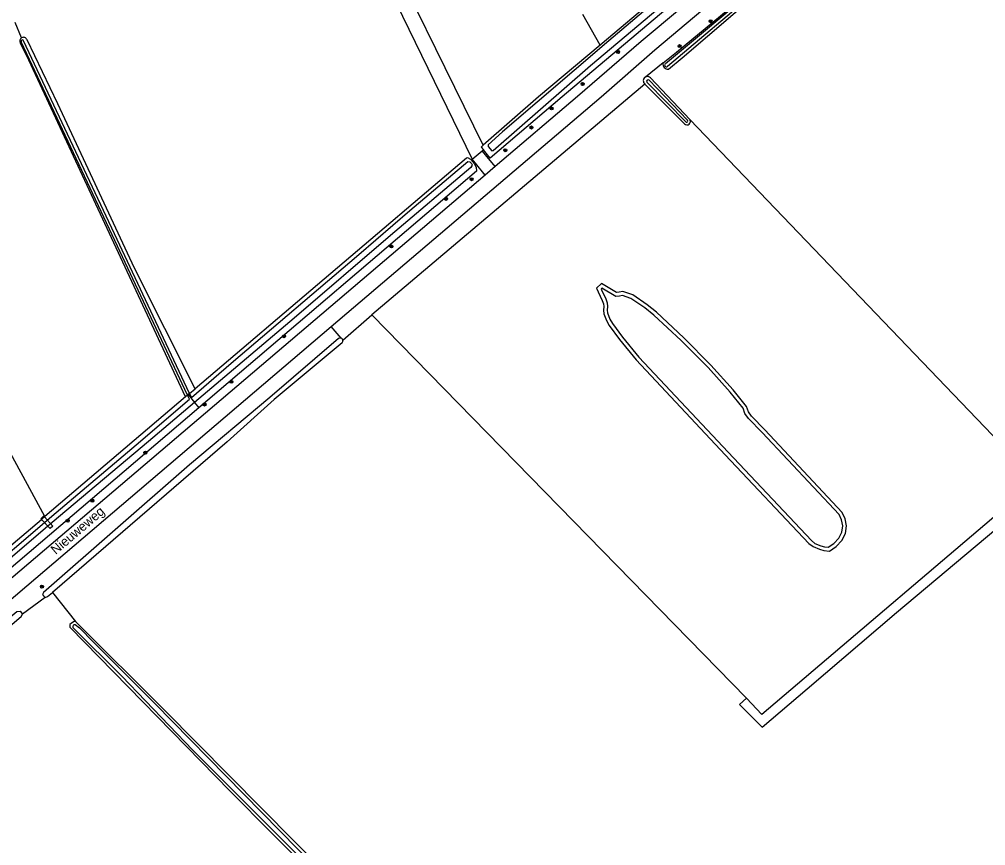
# Model space of a CAD drawing. Extents: x 141000 to 143000, y 400580 to 403500.
# Drawn here: x 141831.6 to 142087.7, y 402801.5 to 403020.5 of the extents above; entities that cross this region are included whole.
import ezdxf

# ---------------------------------------------------------------- set-up
doc = ezdxf.new("R2010")
doc.units = 0
for name, color, linetype in [('gg-afsc-erfafscheiding', 7, 'Continuous'), ('gg-anno-openbare ruimte label', 7, 'Continuous'), ('gg-knt-bronhoudergrens', 7, 'Continuous'), ('gg-knt-onverhard', 7, 'Continuous'), ('gg-knt-verharding', 7, 'Continuous'), ('gg-knt-verharding nz', 7, 'Continuous'), ('gg-kntw-bovenkant insteek waterloop', 7, 'Continuous'), ('gg-kntw-waterlijn', 7, 'Continuous'), ('gg-kwrk-kunstwerk niveau 01', 7, 'Continuous'), ('gt-grn-groengrens', 7, 'Continuous'), ('gt-grn-groengrens NZ', 7, 'Continuous'), ('gt-grn-vlakafsluiter', 7, 'Continuous'), ('gt-symb-boom', 7, 'Continuous')]:
    doc.layers.add(name, color=color, linetype=linetype)

# ---------------------------------------------------------------- blocks, each defined once
blk = doc.blocks.new('gt0-BOOM')
at = {"layer": 'gt-symb-boom'}
for radius in [0.4, 0.2]:
    blk.add_circle((0, 0), radius, dxfattribs=at)

msp = doc.modelspace()

# ---------------------------------------------------------------- linework, layer by layer
at = {"layer": 'gg-afsc-erfafscheiding'}
msp.add_line((141954.24, 402985.64), (141954.6, 402985.93), dxfattribs=at)
at = {"layer": 'gg-knt-bronhoudergrens'}
for p, q in [((141985.53, 403013.64), (141980.91, 403021.8)), ((141838.43, 402888.78), (141779.26, 402997.04)), ((142101.08, 402898.11), (142009.26, 402994.01)), ((141951.61, 402983.49), (141951.33, 402983.25)), ((141917.32, 402935.51), (141925.02, 402942.19)), ((142024.33, 402840.61), (141925.02, 402942.19)), ((141838.51, 402867.33), (141832.48, 402862.85))]:
    msp.add_line(p, q, dxfattribs=at)
for points in [[(141954.53, 402987.13), (141924.4, 403048.52), (141955.72, 403068.45)], [(141886.23, 403053.07), (141911.29, 403066.42), (141951.61, 402983.49)], [(142024.33, 402840.61), (142022.47, 402838.91), (142028.48, 402832.9), (142040.38, 402843.06), (142064.01, 402863.29), (142090.33, 402885.42), (142125.51, 402915.15), (142155.54, 402940.68), (142156.57, 402939.65), (142164.47, 402946.13), (142180.6, 402935.22), (142189.91, 402945.16)], [(142101.08, 402898.11), (142028.36, 402836.3), (142024.33, 402840.61)]]:
    msp.add_lwpolyline(points, dxfattribs=at)
at = {"layer": 'gg-knt-onverhard'}
for p, q in [((141832.25, 403015.61), (141830.54, 403019.7)), ((141840.41, 402868.64), (141846.55, 402860.98))]:
    msp.add_line(p, q, dxfattribs=at)
at = {"layer": 'gg-knt-verharding'}
for p, q in [((141951.61, 402983.49), (141954.24, 402985.64)), ((141955.04, 402979.19), (141652.93, 402722.12)), ((141655.26, 402718.53), (141914.25, 402939.09))]:
    msp.add_line(p, q, dxfattribs=at)
for points in [[(142113.94, 403114.98), (142069.01, 403075.7), (142040.23, 403051.3), (141996.37, 403014.63), (141979.56, 403000.04), (141957.73, 402981.47)], [(141914.25, 402939.09), (141985.78, 403000), (142000, 403012.42), (142042.58, 403048.33), (142071.63, 403072.64), (142109.08, 403104.56)], [(141957.73, 402981.47), (141955.12, 402984.6), (141954.24, 402985.64)], [(141955.04, 402979.19), (141952.51, 402982.36), (141951.61, 402983.49)]]:
    msp.add_lwpolyline(points, dxfattribs=at)
at = {"layer": 'gg-knt-verharding nz'}
msp.add_line((141957.73, 402981.47), (141955.04, 402979.19), dxfattribs=at)
at = {"layer": 'gg-kntw-bovenkant insteek waterloop'}
for p, q in [((141997.4, 403003.37), (142007.84, 402992.79)), ((141998.87, 403005), (142009.26, 402994.01)), ((141875.67, 402920.43), (141838.43, 402888.78)), ((141879.18, 402917.54), (141752.42, 402809.49)), ((141828.25, 402880.12), (141837.5, 402887.99)), ((141838.27, 402888.64), (141837.5, 402887.99)), ((141838.43, 402888.78), (141838.27, 402888.64))]:
    msp.add_line(p, q, dxfattribs=at)
for points in [[(142083.49, 403097.31), (142058.98, 403076.57), (142039.22, 403059.63), (141999.46, 403025.46), (141985.53, 403013.64)], [(142086.98, 403094.57), (142068.18, 403078.4), (142035.98, 403051.05), (141975.46, 403000), (141956.43, 402983.68), (141954.6, 402985.93)], [(142002.23, 403008.95), (142005.78, 403011.79), (142027.06, 403029.52), (142066.63, 403063.32), (142070.81, 403066.65), (142103.18, 403094.88)], [(142003.62, 403007.33), (142007.25, 403010.28), (142028.05, 403028.17), (142067.65, 403062.22), (142071.61, 403065.62), (142104.32, 403093.73)], [(141875.67, 402920.43), (141834.12, 403009.73), (141831.96, 403014.19)], [(141878.25, 402922.62), (141862.14, 402954.54), (141841.82, 402998.14), (141833.68, 403015.1)], [(141985.53, 403013.64), (141969.18, 403000), (141954.53, 402987.13)], [(141954.53, 402987.13), (141954, 402986.66), (141954.6, 402985.93)], [(141951.33, 402983.25), (141951.25, 402983.35), (141950.49, 402983.79), (141950.09, 402983.7), (141878.25, 402922.62)], [(141951.33, 402983.25), (141952.16, 402982.34), (141952.69, 402981.35), (141952.79, 402980.3), (141879.18, 402917.54)], [(142041.94, 402880.78), (142043.64, 402880.08), (142044.82, 402879.71), (142046.25, 402879.59), (142048.08, 402880.84), (142049.6, 402882.41), (142050.57, 402884.3), (142050.8, 402886.28), (142050.47, 402888.18), (142049.67, 402889.83), (142029.18, 402911.72), (142025.62, 402915.36), (142024.79, 402916.53), (142024.33, 402917.92), (142020.73, 402922.36), (142014.86, 402928.91), (142007.71, 402936.09), (142000.42, 402942.91), (141997.97, 402944.85), (141994.15, 402947.47), (141991.57, 402948.38), (141990.52, 402948.17), (141989.9, 402948.12), (141985.85, 402950.55), (141984.59, 402949.25), (141984.98, 402948.31), (141986.07, 402946.04), (141986.4, 402945.16), (141986.46, 402944.37), (141986.41, 402943.42), (141986.5, 402942.48), (141987.17, 402940.66), (141987.94, 402939.36), (141990.63, 402935.7), (141995.05, 402930.3), (142018.68, 402905.13), (142040.82, 402881.64), (142041.94, 402880.78)], [(141916.2, 402935.94), (141898.04, 402920.26), (141876.73, 402902.48), (141838.07, 402868.65), (141837.81, 402868.13), (141838.02, 402867.74), (141838.51, 402867.33)], [(141917.17, 402934.79), (141899.16, 402919.76), (141886.73, 402908.59), (141840.41, 402868.64)], [(141838.51, 402867.33), (141839.14, 402867.55), (141840.41, 402868.64)], [(141766.76, 402806.55), (141765.9, 402807.03), (141766.43, 402808.44), (141818.23, 402853.06), (141831.01, 402863.57), (141831.86, 402863.7), (141832.48, 402862.85)], [(141766.76, 402806.55), (141767.55, 402806.99), (141773.9, 402812.52), (141832.12, 402862.23), (141832.48, 402862.85)], [(141846.55, 402860.98), (141846.19, 402860.92), (141845.44, 402860.46), (141845.05, 402860.12), (141845.06, 402859.46)], [(141846.55, 402860.98), (141870.14, 402837.41), (141938.81, 402768.01), (141943.3, 402763.5), (141943.19, 402762.94), (141942.81, 402762.27)], [(141942.81, 402762.27), (141942.47, 402761.99), (141942, 402761.7), (141941.63, 402761.72), (141920.66, 402782.6), (141887.53, 402816.01), (141845.06, 402859.46)]]:
    msp.add_lwpolyline(points, dxfattribs=at)
for centre, radius, start, end in [((141832.76, 403014.77), 0.981, 121.0463, 215.7734), ((141832.76, 403014.77), 0.98, 20.032, 120.9408), ((142003.43, 403008.57), 1.26, 162.3098, 278.5847), ((141998.05, 403004.26), 1.1, 118.358, 233.8424), ((141998.05, 403004.26), 1.1, 42.2594, 118.3732), ((142008.49, 402993.48), 0.94, 226.7215, 34.5609), ((141916.59, 402935.28), 0.765, 67.168, 120.8023), ((141916.59, 402935.29), 0.764, 17.3442, 67.1073), ((141916.59, 402935.29), 0.764, 319.5499, 17.3126)]:
    msp.add_arc(centre, radius, start, end, dxfattribs=at)
at = {"layer": 'gg-kntw-waterlijn'}
for p, q in [((141997.87, 403003.88), (142008.29, 402993.29)), ((141998.5, 403004.35), (142008.67, 402993.76))]:
    msp.add_line(p, q, dxfattribs=at)
for points in [[(142084.73, 403097.25), (142038.86, 403058.08), (141987.86, 403014.78), (141959.64, 402990.67), (141955.88, 402987.28), (141955.84, 402986.83), (141956.8, 402985.67), (141957.16, 402985.73), (141982.98, 403008.3), (142006.38, 403028.11), (142029.12, 403047.51), (142056.27, 403070.88), (142085.54, 403095.68), (142085.84, 403095.93)], [(142103.33, 403094.3), (142071.13, 403066.27), (142066.95, 403062.93), (142027.34, 403029.19), (142002.8, 403008.76)], [(142103.77, 403093.92), (142071.28, 403066), (142067.33, 403062.6), (142027.66, 403028.61), (142003.39, 403008.02)], [(141876.21, 402920.89), (141856.22, 402963.37), (141832.15, 403014.55)], [(141876.76, 402921.36), (141856.85, 402963.67), (141832.78, 403014.84)], [(141876.76, 402921.36), (141877.24, 402920.33), (141887.77, 402929.4), (141921.61, 402958.22), (141935.06, 402969.88), (141950.49, 402982.83), (141950.98, 402982.78), (141951.43, 402982.29), (141951.58, 402981.94), (141951.52, 402981.65), (141951.28, 402981.29), (141929.96, 402963.23), (141904.43, 402941.32), (141878.05, 402918.98)], [(142042.44, 402881.65), (142043.98, 402881.02), (142045.01, 402880.69), (142045.98, 402880.62), (142047.43, 402881.6), (142048.78, 402883), (142049.59, 402884.6), (142049.79, 402886.25), (142049.51, 402887.87), (142048.83, 402889.26), (142028.46, 402911.03), (142024.85, 402914.72), (142023.89, 402916.07), (142023.43, 402917.43), (142019.97, 402921.71), (142014.14, 402928.23), (142007.01, 402935.37), (141999.77, 402942.15), (141997.37, 402944.04), (141993.69, 402946.57), (141991.49, 402947.34), (141990.66, 402947.18), (141989.66, 402947.1), (141986.01, 402949.28), (141985.77, 402949.03), (141986.99, 402946.43), (141987.38, 402945.38), (141987.46, 402944.38), (141987.41, 402943.45), (141987.49, 402942.7), (141988.07, 402941.09), (141988.78, 402939.92), (141991.42, 402936.31), (141995.8, 402930.96), (142019.41, 402905.81), (142041.49, 402882.38), (142042.44, 402881.65)], [(141750.09, 402812.04), (141792.04, 402847.68), (141818.62, 402870.43), (141841.36, 402889.82), (141862.6, 402907.71), (141876.69, 402919.86), (141876.21, 402920.89)], [(141878.05, 402918.98), (141865.9, 402908.68), (141840.3, 402887.18), (141786.58, 402841.13), (141757.42, 402816.47), (141751.02, 402811.02)], [(141877.65, 402826.88), (141858.8, 402846.44), (141845.91, 402859.22), (141845.87, 402859.62), (141845.96, 402859.93), (141846.16, 402860.14), (141846.44, 402860.14), (141847.55, 402859.3), (141851.32, 402855.45), (141867.51, 402839.18), (141891.13, 402815.22), (141919.62, 402786.11), (141942.7, 402763.15), (141942.36, 402762.56), (141941.96, 402762.29), (141934.83, 402769.15), (141903.85, 402800.56), (141877.65, 402826.88)]]:
    msp.add_lwpolyline(points, dxfattribs=at)
for centre, radius, start, end in [((141832.46, 403014.71), 0.35, 23.1717, 207.1783), ((142003.09, 403008.39), 0.478, 128.5752, 308.5008), ((141998.22, 403004.08), 0.397, 43.9981, 209.2761), ((142008.46, 402993.54), 0.305, 235.4241, 46.7265)]:
    msp.add_arc(centre, radius, start, end, dxfattribs=at)
at = {"layer": 'gg-kwrk-kunstwerk niveau 01'}
for points in [[(141838.27, 402888.64), (141838.07, 402888.84), (141837.34, 402888.16), (141837.5, 402887.99)], [(141838.27, 402888.64), (141840.5, 402886.24), (141839.77, 402885.55), (141837.5, 402887.99)]]:
    msp.add_lwpolyline(points, dxfattribs=at)
at = {"layer": 'gt-grn-groengrens'}
for p, q in [((141997.4, 403003.37), (141925.02, 402942.19)), ((141916.89, 402935.99), (141914.25, 402939.09))]:
    msp.add_line(p, q, dxfattribs=at)
at = {"layer": 'gt-grn-groengrens NZ'}
msp.add_line((142002.23, 403008.95), (141997.53, 403005.23), dxfattribs=at)
at = {"layer": 'gt-grn-vlakafsluiter'}
for p, q in [((141876.76, 402921.36), (141876.41, 402921.06)), ((141876.76, 402921.36), (141878.25, 402922.62)), ((141876.21, 402920.89), (141875.67, 402920.43)), ((141876.41, 402921.06), (141876.21, 402920.89)), ((141876.41, 402921.06), (141878.05, 402918.98)), ((141878.05, 402918.98), (141879.18, 402917.54))]:
    msp.add_line(p, q, dxfattribs=at)

# ---------------------------------------------------------------- block references
at = {"layer": 'gt-symb-boom'}
for p in [(142014.77, 403020.01), (142006.57, 403013.41), (141990.26, 403011.86), (141980.88, 403003.38), (141972.66, 402996.89), (141967.32, 402991.85), (141960.4, 402985.83), (141951.46, 402978.14), (141944.69, 402972.94), (141930.21, 402960.32), (141901.78, 402936.53), (141887.85, 402924.47), (141880.7, 402918.42), (141865.04, 402905.69), (141851.02, 402892.95), (141844.46, 402887.66), (141837.64, 402870.18)]:
    msp.add_blockref('gt0-BOOM', p, dxfattribs=at)

# ---------------------------------------------------------------- texts
at = {"layer": 'gg-anno-openbare ruimte label'}
msp.add_text('Nieuweweg', height=2.5, rotation=40.4, dxfattribs=at).set_placement((141841.29, 402878.55))

doc.saveas('drawing.dxf')
